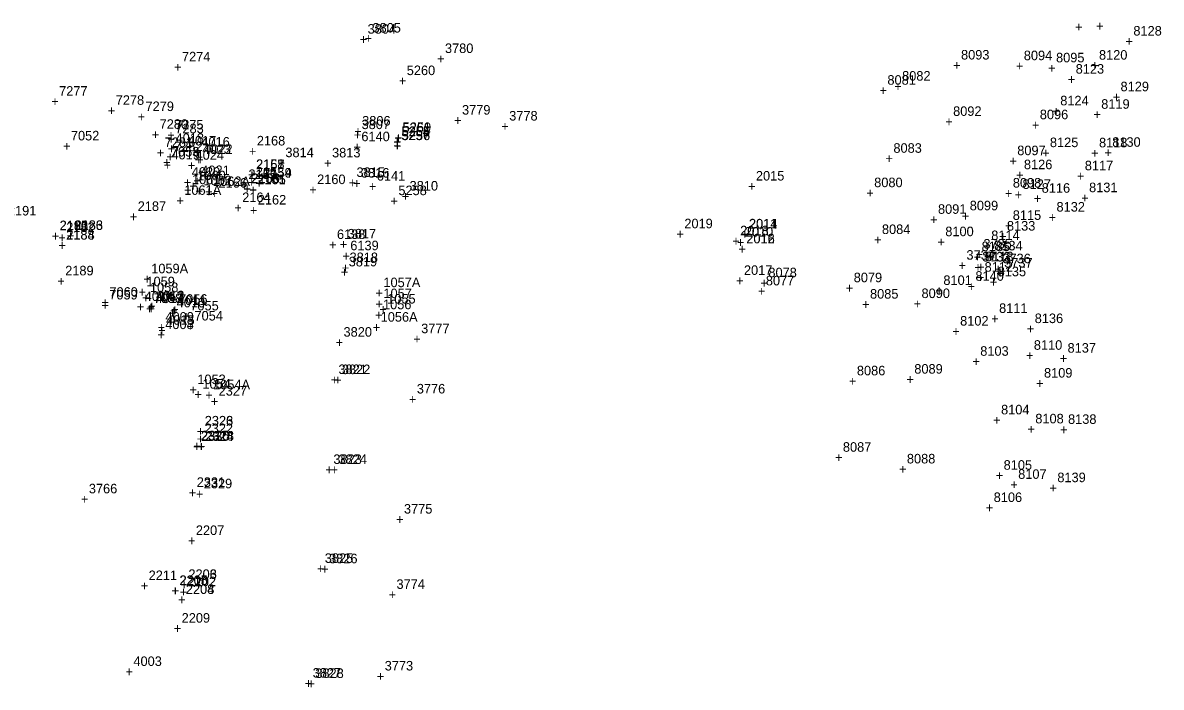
# Model space of a CAD drawing. Extents: x 1136220 to 1137808, y 528804 to 531215.
# Drawn here: x 1137337.9 to 1137635.9, y 529893.5 to 530067.6 of the extents above; entities that cross this region are included whole.
import ezdxf

# ---------------------------------------------------------------- set-up
doc = ezdxf.new("R2010")
doc.units = 0
for name, color, linetype in [('S_Buildings_SillElevation', 7, 'Continuous'), ('S_Curb_Type_1', 7, 'Continuous'), ('S_Drainage_CB', 7, 'Continuous'), ('S_Drainage_Culvert_Top', 7, 'Continuous'), ('S_Drainage_Invert', 7, 'Continuous'), ('S_Drainage_Sump', 7, 'Continuous'), ('S_Ground_Elevation', 7, 'Continuous'), ('S_Ground_SpotElevation', 7, 'Continuous'), ('S_Misc_MiscItems', 7, 'Continuous'), ('S_Roadway_Drive_Gravel', 7, 'Continuous'), ('S_Roadway_Drive_Paved', 7, 'Continuous'), ('S_Roadway_Edge_Pavement', 7, 'Continuous'), ('S_Trees_Decid_Pay', 7, 'Continuous'), ('S_Utilities_UG_Sanitary_MH', 7, 'Continuous'), ('S_Utilities_UG_Telephone', 7, 'Continuous'), ('S_Utilities_UG_Water_Gate', 7, 'Continuous'), ('S_Utilities_UG_Water_Line', 7, 'Continuous'), ('S_Utilities_UG_Water_Shutoff', 7, 'Continuous')]:
    doc.layers.add(name, color=color, linetype=linetype)

msp = doc.modelspace()

# ---------------------------------------------------------------- texts
at = {"layer": 'S_Buildings_SillElevation'}
for s, p in [('3780', (1137448.42, 530059.62)), ('+', (1137446.36, 530056.87)), ('3779', (1137452.89, 530043.49)), ('+', (1137450.83, 530040.74)), ('3778', (1137465.24, 530041.94)), ('+', (1137463.17, 530039.19)), ('3777', (1137442.19, 529986.23)), ('+', (1137440.13, 529983.48)), ('3776', (1137441.05, 529970.44)), ('+', (1137438.99, 529967.69)), ('3766', (1137355.21, 529944.28)), ('+', (1137353.15, 529941.53)), ('3775', (1137437.69, 529938.98)), ('+', (1137435.63, 529936.23)), ('3774', (1137435.73, 529919.26)), ('+', (1137433.67, 529916.51)), ('4003', (1137366.88, 529899.06)), ('3773', (1137432.65, 529897.88)), ('+', (1137364.82, 529896.31)), ('+', (1137430.59, 529895.13))]:
    msp.add_text(s, height=2.5, dxfattribs=at).set_placement(p)
at = {"layer": 'S_Curb_Type_1'}
for s, p in [('7059', (1137360.56, 529995.07)), ('+', (1137358.5, 529992.32)), ('7058', (1137372.2, 529994.14)), ('+', (1137370.14, 529991.39))]:
    msp.add_text(s, height=2.5, dxfattribs=at).set_placement(p)
at = {"layer": 'S_Drainage_CB'}
for s, p in [('5254', (1137437.03, 530037.81)), ('+', (1137434.96, 530035.06))]:
    msp.add_text(s, height=2.5, dxfattribs=at).set_placement(p)
at = {"layer": 'S_Drainage_Culvert_Top'}
for s, p in [('5260', (1137438.42, 530053.84)), ('+', (1137436.36, 530051.09)), ('5257', (1137436.99, 530036.83)), ('5259', (1137437.37, 530038.94)), ('2168', (1137399.18, 530035.41)), ('+', (1137434.93, 530034.08)), ('+', (1137435.31, 530036.19)), ('+', (1137397.12, 530032.66)), ('2167', (1137399.01, 530029.23)), ('1062A', (1137387.71, 530024.77)), ('+', (1137396.95, 530026.48)), ('2165', (1137397, 530026.62)), ('2163', (1137397.74, 530025.53)), ('2161', (1137399.29, 530025.22)), ('2159', (1137400.87, 530027.01)), ('2160', (1137414.96, 530025.29)), ('2015', (1137529.81, 530026.22)), ('1061A', (1137380.19, 530022.47)), ('+', (1137385.65, 530022.02)), ('2166', (1137389.15, 530024.35)), ('+', (1137394.94, 530023.87)), ('+', (1137395.68, 530022.78)), ('+', (1137397.23, 530022.47)), ('+', (1137398.81, 530024.26)), ('+', (1137412.9, 530022.54)), ('5258', (1137436.23, 530022.39)), ('+', (1137527.75, 530023.47)), ('+', (1137378.13, 530019.72)), ('+', (1137387.09, 530021.6)), ('2164', (1137395.35, 530020.58)), ('2162', (1137399.43, 530019.94)), ('+', (1137434.17, 530019.64)), ('2191', (1137334.02, 530017.07)), ('2187', (1137368, 530018.26)), ('+', (1137393.29, 530017.83)), ('+', (1137397.37, 530017.19)), ('2190', (1137347.55, 530013.2)), ('2186', (1137351.45, 530013.3)), ('+', (1137365.94, 530015.51)), ('2019', (1137511.08, 530013.71)), ('2014', (1137528.01, 530013.65)), ('+', (1137345.48, 530010.45)), ('2188', (1137349.27, 530010.77)), ('+', (1137349.38, 530010.55)), ('+', (1137509.02, 530010.96)), ('2018', (1137525.69, 530011.86)), ('+', (1137525.95, 530010.9)), ('2016', (1137527.31, 530009.76)), ('+', (1137347.21, 530008.02)), ('+', (1137523.63, 530009.11)), ('3735', (1137589.36, 530008.39)), ('+', (1137525.25, 530007.01)), ('3734', (1137584.91, 530005.48)), ('+', (1137587.3, 530005.64)), ('2189', (1137349.02, 530001.38)), ('1059A', (1137371.54, 530001.92)), ('2017', (1137526.68, 530001.5)), ('+', (1137582.85, 530002.73)), ('+', (1137346.96, 529998.63)), ('+', (1137369.48, 529999.17)), ('1057A', (1137432.31, 529998.29)), ('+', (1137524.62, 529998.75)), ('+', (1137430.25, 529995.54)), ('1056A', (1137431.59, 529989.25)), ('+', (1137429.53, 529986.5)), ('1054A', (1137387.74, 529971.53)), ('+', (1137385.68, 529968.78)), ('2327', (1137389.18, 529969.89)), ('+', (1137387.12, 529967.14)), ('2326', (1137385.54, 529962.06)), ('+', (1137383.48, 529959.31)), ('2330', (1137384.55, 529958.03)), ('2328', (1137385.77, 529958.11)), ('+', (1137382.49, 529955.28)), ('+', (1137383.71, 529955.36)), ('2331', (1137383.45, 529945.97)), ('2329', (1137385.29, 529945.6)), ('+', (1137381.39, 529943.22)), ('+', (1137383.23, 529942.85)), ('2207', (1137383.22, 529933.37)), ('+', (1137381.16, 529930.62)), ('2211', (1137370.86, 529921.56)), ('2210', (1137378.98, 529920.26)), ('2206', (1137381.27, 529921.87)), ('+', (1137368.8, 529918.81)), ('+', (1137379.21, 529919.12)), ('2208', (1137380.61, 529917.94)), ('+', (1137376.92, 529917.51)), ('+', (1137378.55, 529915.19)), ('2209', (1137379.5, 529910.41)), ('+', (1137377.44, 529907.66))]:
    msp.add_text(s, height=2.5, dxfattribs=at).set_placement(p)
at = {"layer": 'S_Drainage_Invert'}
for s, p in [('5256', (1137437.11, 530036.8)), ('5261', (1137437.28, 530038.84)), ('+', (1137435.05, 530034.05)), ('+', (1137435.22, 530036.09)), ('2158', (1137398.97, 530029.26)), ('1061', (1137382.21, 530025.26)), ('1062', (1137385.18, 530024.99)), ('+', (1137396.91, 530026.51)), ('2157', (1137396.97, 530026.62)), ('2156', (1137397.71, 530025.6)), ('2155', (1137399.32, 530025.29)), ('2154', (1137400.86, 530027.01)), ('+', (1137380.15, 530022.51)), ('+', (1137383.12, 530022.24)), ('+', (1137394.91, 530023.87)), ('+', (1137395.65, 530022.85)), ('+', (1137397.26, 530022.54)), ('+', (1137398.8, 530024.26)), ('2185', (1137347.58, 530013.23)), ('2183', (1137351.48, 530013.27)), ('2011', (1137527.98, 530013.68)), ('+', (1137345.52, 530010.48)), ('2184', (1137349.3, 530010.74)), ('+', (1137349.42, 530010.52)), ('2013', (1137525.7, 530011.87)), ('+', (1137525.92, 530010.93)), ('2012', (1137527.28, 530009.78)), ('+', (1137347.24, 530007.99)), ('+', (1137523.63, 530009.12)), ('+', (1137525.22, 530007.03)), ('3733', (1137589.03, 530005.01)), ('3736', (1137594.32, 530004.56)), ('+', (1137586.97, 530002.26)), ('+', (1137592.26, 530001.81)), ('3737', (1137594.8, 530003.44)), ('1059', (1137370.28, 529998.53)), ('+', (1137592.74, 530000.69)), ('+', (1137368.22, 529995.78)), ('1057', (1137432.31, 529995.41)), ('+', (1137430.25, 529992.66)), ('1056', (1137432.21, 529992.51)), ('+', (1137430.15, 529989.76)), ('1054', (1137384.93, 529971.7)), ('+', (1137382.87, 529968.95)), ('2323', (1137385.56, 529962.06)), ('+', (1137383.5, 529959.31)), ('2325', (1137384.59, 529958.17)), ('2324', (1137385.64, 529958.03)), ('+', (1137382.53, 529955.42)), ('+', (1137383.58, 529955.28)), ('2205', (1137378.91, 529920.28)), ('2203', (1137381.26, 529921.86)), ('+', (1137379.2, 529919.11)), ('2204', (1137380.59, 529917.92)), ('+', (1137376.84, 529917.53)), ('+', (1137378.53, 529915.17))]:
    msp.add_text(s, height=2.5, dxfattribs=at).set_placement(p)
at = {"layer": 'S_Drainage_Sump'}
for s, p in [('5255', (1137437.1, 530037.9)), ('+', (1137435.03, 530035.15)), ('1060', (1137383.6, 530026.3)), ('+', (1137381.54, 530023.55)), ('1058', (1137371.2, 529997)), ('+', (1137369.14, 529994.25)), ('1055', (1137433.3, 529994)), ('+', (1137431.24, 529991.25)), ('1053', (1137383.6, 529972.9)), ('+', (1137381.54, 529970.15))]:
    msp.add_text(s, height=2.5, dxfattribs=at).set_placement(p)
at = {"layer": 'S_Ground_Elevation'}
for s, p in [('+', (1137613.38, 530065.22)), ('+', (1137618.87, 530065.45)), ('8128', (1137628.61, 530064.2)), ('+', (1137626.55, 530061.45)), ('8093', (1137583.5, 530057.92)), ('8094', (1137599.93, 530057.74)), ('8120', (1137619.61, 530057.88)), ('+', (1137581.44, 530055.17)), ('+', (1137597.87, 530054.99)), ('8095', (1137608.37, 530057.18)), ('+', (1137617.55, 530055.13)), ('8082', (1137568.08, 530052.39)), ('+', (1137606.31, 530054.43)), ('8123', (1137613.51, 530054.22)), ('+', (1137566.02, 530049.64)), ('+', (1137611.45, 530051.47)), ('8129', (1137625.25, 530049.6)), ('8124', (1137609.47, 530045.91)), ('+', (1137623.19, 530046.85)), ('8092', (1137581.43, 530043.15)), ('+', (1137607.41, 530043.16)), ('8119', (1137620.19, 530045.02)), ('+', (1137579.37, 530040.4)), ('8096', (1137604.12, 530042.28)), ('+', (1137618.13, 530042.27)), ('+', (1137602.06, 530039.53)), ('4018', (1137377.91, 530036.07)), ('4017', (1137381.11, 530035.4)), ('4016', (1137384.66, 530035.11)), ('8083', (1137565.8, 530033.49)), ('8125', (1137606.76, 530034.97)), ('8118', (1137619.62, 530034.91)), ('8130', (1137623.08, 530035.06)), ('+', (1137375.85, 530033.32)), ('4019', (1137376.83, 530031.75)), ('+', (1137379.05, 530032.65)), ('+', (1137382.6, 530032.36)), ('4023', (1137384.95, 530033.19)), ('4022', (1137385.4, 530033.18)), ('8097', (1137598.21, 530032.86)), ('+', (1137604.7, 530032.22)), ('+', (1137617.56, 530032.16)), ('+', (1137621.02, 530032.31)), ('+', (1137374.77, 530029)), ('+', (1137382.89, 530030.44)), ('+', (1137383.34, 530030.43)), ('4021', (1137384.65, 530027.65)), ('+', (1137563.74, 530030.74)), ('+', (1137596.15, 530030.11)), ('8126', (1137599.96, 530029.19)), ('8117', (1137615.9, 530028.91)), ('4020', (1137382.14, 530027.22)), ('+', (1137597.9, 530026.44)), ('+', (1137613.84, 530026.16)), ('+', (1137380.08, 530024.47)), ('+', (1137382.58, 530024.9)), ('8098', (1137597.06, 530024.38)), ('8127', (1137599.59, 530024.03)), ('8116', (1137604.62, 530023.02)), ('8131', (1137617.02, 530023.17)), ('+', (1137595, 530021.63)), ('+', (1137597.53, 530021.28)), ('+', (1137602.56, 530020.27)), ('+', (1137614.96, 530020.42)), ('8091', (1137577.47, 530017.5)), ('8099', (1137585.78, 530018.42)), ('8115', (1137597.04, 530015.91)), ('8132', (1137608.49, 530018.09)), ('+', (1137575.41, 530014.75)), ('+', (1137583.72, 530015.67)), ('+', (1137594.98, 530013.16)), ('8133', (1137595.51, 530013.11)), ('+', (1137606.43, 530015.34)), ('8084', (1137562.8, 530012.21)), ('8100', (1137579.38, 530011.64)), ('8114', (1137591.41, 530010.62)), ('+', (1137593.45, 530010.36)), ('+', (1137560.74, 530009.46)), ('+', (1137577.32, 530008.89)), ('+', (1137589.35, 530007.87)), ('8134', (1137592.18, 530007.92)), ('8113', (1137589.79, 530005.07)), ('+', (1137590.12, 530005.17)), ('+', (1137587.73, 530002.32)), ('8112', (1137589.66, 530002.34)), ('8135', (1137593.09, 530001.15)), ('8101', (1137578.88, 529998.87)), ('+', (1137587.6, 529999.59)), ('+', (1137591.03, 529998.4)), ('4012', (1137372.77, 529994.86)), ('8085', (1137559.68, 529995.29)), ('8090', (1137573.16, 529995.44)), ('+', (1137576.82, 529996.12)), ('4014', (1137369.83, 529994.65)), ('4013', (1137372.63, 529994.12)), ('4010', (1137378.2, 529992.99)), ('4011', (1137378.54, 529993.62)), ('+', (1137557.62, 529992.54)), ('+', (1137571.09, 529992.69)), ('+', (1137367.77, 529991.9)), ('+', (1137370.56, 529991.37)), ('+', (1137370.71, 529992.11)), ('4009', (1137375.26, 529989.26)), ('+', (1137376.14, 529990.24)), ('+', (1137376.47, 529990.87)), ('8111', (1137593.46, 529991.54)), ('8136', (1137602.79, 529988.88)), ('+', (1137373.2, 529986.51)), ('4008', (1137375.21, 529987.31)), ('8102', (1137583.26, 529988.22)), ('+', (1137591.4, 529988.79)), ('+', (1137373.14, 529984.56)), ('+', (1137581.2, 529985.47)), ('+', (1137600.73, 529986.13)), ('8103', (1137588.53, 529980.32)), ('8110', (1137602.56, 529981.89)), ('8137', (1137611.38, 529981.13)), ('+', (1137586.47, 529977.58)), ('+', (1137600.5, 529979.14)), ('+', (1137609.32, 529978.38)), ('8086', (1137556.24, 529975.19)), ('8089', (1137571.27, 529975.64)), ('8109', (1137605.22, 529974.6)), ('+', (1137554.17, 529972.44)), ('+', (1137569.21, 529972.89)), ('+', (1137603.16, 529971.85)), ('8104', (1137593.98, 529964.97)), ('8108', (1137602.94, 529962.61)), ('8138', (1137611.51, 529962.47)), ('+', (1137591.92, 529962.22)), ('+', (1137600.88, 529959.86)), ('+', (1137609.45, 529959.72)), ('8087', (1137552.58, 529955.18)), ('+', (1137550.52, 529952.43)), ('8088', (1137569.33, 529952.12)), ('8105', (1137594.65, 529950.47)), ('+', (1137567.27, 529949.37)), ('+', (1137592.59, 529947.72)), ('8107', (1137598.46, 529948.08)), ('8139', (1137608.71, 529947.21)), ('+', (1137596.4, 529945.33)), ('8106', (1137592.05, 529942.02)), ('+', (1137606.65, 529944.46)), ('+', (1137589.99, 529939.27))]:
    msp.add_text(s, height=2.5, dxfattribs=at).set_placement(p)
at = {"layer": 'S_Ground_SpotElevation'}
for s, p in [('4024', (1137383.14, 530031.66)), ('+', (1137381.08, 530028.91)), ('4015', (1137375.45, 529988.44)), ('+', (1137373.39, 529985.69))]:
    msp.add_text(s, height=2.5, dxfattribs=at).set_placement(p)
at = {"layer": 'S_Misc_MiscItems'}
for s, p in [('8185', (1137588.88, 530007.71)), ('+', (1137586.82, 530004.96))]:
    msp.add_text(s, height=2.5, dxfattribs=at).set_placement(p)
at = {"layer": 'S_Roadway_Drive_Gravel'}
for s, p in [('7274', (1137379.58, 530057.43)), ('+', (1137377.52, 530054.68)), ('8081', (1137564.23, 530051.32)), ('+', (1137562.17, 530048.57)), ('7275', (1137377.79, 530039.61)), ('7283', (1137377.85, 530038.61)), ('+', (1137375.73, 530036.86)), ('+', (1137375.79, 530035.86)), ('8080', (1137560.77, 530024.48)), ('+', (1137558.71, 530021.73)), ('8078', (1137533.08, 530000.88)), ('8077', (1137532.41, 529998.76)), ('8079', (1137555.41, 529999.58)), ('+', (1137530.35, 529996.01)), ('+', (1137531.01, 529998.13)), ('+', (1137553.35, 529996.83))]:
    msp.add_text(s, height=2.5, dxfattribs=at).set_placement(p)
at = {"layer": 'S_Roadway_Drive_Paved'}
for s, p in [('7277', (1137347.43, 530048.44)), ('7278', (1137362.24, 530046.05)), ('+', (1137345.37, 530045.69)), ('+', (1137360.18, 530043.3)), ('7279', (1137370.04, 530044.42)), ('+', (1137367.98, 530041.67)), ('7280', (1137373.73, 530039.77)), ('+', (1137371.67, 530037.02)), ('7281', (1137375.04, 530035)), ('7282', (1137377.58, 530033.93)), ('+', (1137372.98, 530032.25)), ('+', (1137375.52, 530031.18))]:
    msp.add_text(s, height=2.5, dxfattribs=at).set_placement(p)
at = {"layer": 'S_Roadway_Edge_Pavement'}
for s, p in [('7052', (1137350.51, 530036.73)), ('+', (1137348.45, 530033.98)), ('7053', (1137376.7, 530032.52)), ('+', (1137374.64, 530029.77)), ('7060', (1137360.59, 529995.78)), ('+', (1137358.53, 529993.03)), ('7057', (1137372.5, 529994.61)), ('7056', (1137378.82, 529993.95)), ('7055', (1137381.77, 529992.2)), ('+', (1137370.44, 529991.86)), ('+', (1137376.76, 529991.2)), ('+', (1137379.71, 529989.45)), ('7054', (1137382.86, 529989.55)), ('+', (1137380.8, 529986.8))]:
    msp.add_text(s, height=2.5, dxfattribs=at).set_placement(p)
at = {"layer": 'S_Trees_Decid_Pay'}
for s, p in [('8140', (1137587.27, 529999.97)), ('+', (1137585.21, 529997.22))]:
    msp.add_text(s, height=2.5, dxfattribs=at).set_placement(p)
at = {"layer": 'S_Utilities_UG_Sanitary_MH'}
for s, p in [('2153', (1137398.91, 530027.27)), ('+', (1137396.85, 530024.52)), ('2182', (1137349.29, 530012.76)), ('2010', (1137526.89, 530011.53)), ('+', (1137347.22, 530010.01)), ('+', (1137524.83, 530008.78)), ('2322', (1137385.51, 529960.06)), ('+', (1137383.45, 529957.31)), ('2202', (1137381.08, 529919.96)), ('+', (1137379.02, 529917.21))]:
    msp.add_text(s, height=2.5, dxfattribs=at).set_placement(p)
at = {"layer": 'S_Utilities_UG_Telephone'}
for s, p in [('3814', (1137406.65, 530032.34)), ('3813', (1137418.87, 530032.28)), ('+', (1137404.59, 530029.59)), ('+', (1137416.81, 530029.53))]:
    msp.add_text(s, height=2.5, dxfattribs=at).set_placement(p)
at = {"layer": 'S_Utilities_UG_Water_Gate'}
for s, p in [('6140', (1137426.54, 530036.52)), ('+', (1137424.47, 530033.77)), ('6141', (1137430.58, 530026.19)), ('+', (1137428.52, 530023.44)), ('6138', (1137420.15, 530010.9)), ('+', (1137418.09, 530008.15)), ('6139', (1137423.64, 530007.96)), ('+', (1137421.58, 530005.21)), ('3820', (1137421.87, 529985.32)), ('+', (1137419.81, 529982.57))]:
    msp.add_text(s, height=2.5, dxfattribs=at).set_placement(p)
at = {"layer": 'S_Utilities_UG_Water_Line'}
for s, p in [('3804', (1137428.17, 530064.69)), ('3805', (1137429.45, 530064.99)), ('+', (1137426.11, 530061.94)), ('+', (1137427.39, 530062.24)), ('3807', (1137426.59, 530039.69)), ('3806', (1137426.75, 530040.62)), ('+', (1137424.53, 530036.94)), ('+', (1137424.69, 530037.87)), ('3815', (1137425.26, 530027.15)), ('3816', (1137426.44, 530026.99)), ('+', (1137423.2, 530024.4)), ('+', (1137424.38, 530024.24)), ('3817', (1137422.96, 530011.04)), ('+', (1137420.9, 530008.29)), ('3819', (1137423.22, 530003.73)), ('3818', (1137423.46, 530004.85)), ('+', (1137421.4, 530002.1)), ('+', (1137421.16, 530000.98)), ('3821', (1137420.54, 529975.53)), ('3822', (1137421.45, 529975.51)), ('+', (1137418.48, 529972.78)), ('+', (1137419.38, 529972.76)), ('3823', (1137419.21, 529951.98)), ('3824', (1137420.55, 529951.98)), ('+', (1137417.15, 529949.23)), ('+', (1137418.49, 529949.23)), ('3825', (1137416.97, 529926.07)), ('3826', (1137418.1, 529925.97)), ('+', (1137414.91, 529923.32)), ('+', (1137416.03, 529923.22)), ('3827', (1137413.8, 529896.01)), ('3828', (1137414.49, 529895.92)), ('+', (1137411.74, 529893.26)), ('+', (1137412.43, 529893.17))]:
    msp.add_text(s, height=2.5, dxfattribs=at).set_placement(p)
at = {"layer": 'S_Utilities_UG_Water_Shutoff'}
for s, p in [('3810', (1137439.17, 530023.6)), ('+', (1137437.11, 530020.85))]:
    msp.add_text(s, height=2.5, dxfattribs=at).set_placement(p)

doc.saveas('drawing.dxf')
